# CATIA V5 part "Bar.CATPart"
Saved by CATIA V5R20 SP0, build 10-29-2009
Part number: Bar
Material "Steel": density 7860 kg/m3, Young's modulus 2e+11 Pa, Poisson ratio 0.266, thermal expansion 1.17e-05 1/K
Bounding box of the stored display mesh (mm): x -12.5 to 12.5, y -12.5 to 12.5, z 0 to 91
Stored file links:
  E:\Ehsan\Amoozesh\CATIA\CATIA Course\Basic\Exercises\Assembly\12\Bar.CATPart
  D:\CATIA V5R20\B20\intel_a\startup\materials\Catalog.CATMaterial
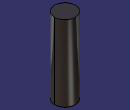
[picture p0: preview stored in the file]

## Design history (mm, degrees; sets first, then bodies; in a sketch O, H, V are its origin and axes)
Body1 (main body), material "Steel"
  Sketch1 on xy-plane, origin (0, 0, 0), H (1, 0, 0), V (0, 1, 0)
    circle A1 centre (0, 0) radius 12.5
  Pad1: profile Sketch1, direction (0, 0, 1), length 91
